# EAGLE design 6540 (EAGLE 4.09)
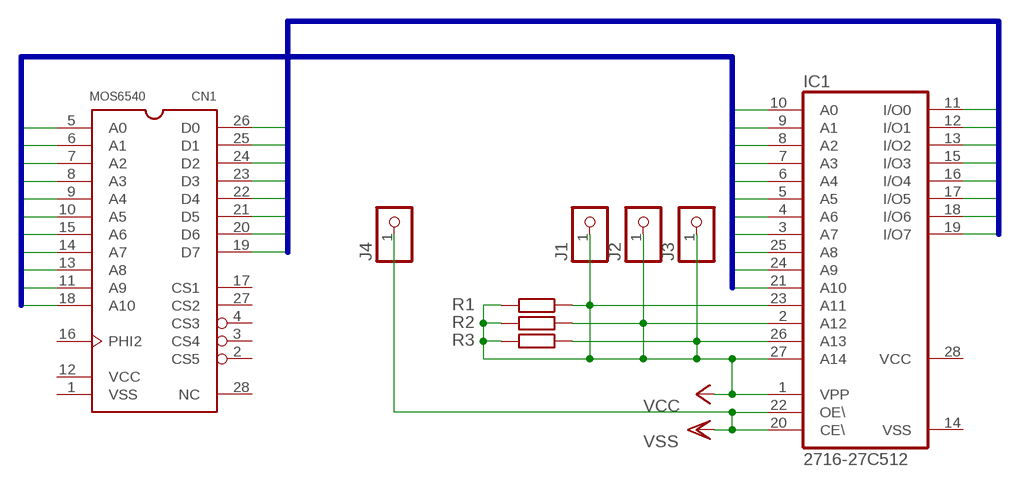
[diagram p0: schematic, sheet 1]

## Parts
CN1  MOS6540  [DIP-28]
IC1  2716-27C512  27C256AG  [DIL28-6]
J1  PINHD-1X1  [1X01]
J2  PINHD-1X1  [1X01]
J3  PINHD-1X1  [1X01]
J4  PINHD-1X1  [1X01]
R1  R-EU_M0805  [M0805]
R2  R-EU_M0805  [M0805]
R3  R-EU_M0805  [M0805]

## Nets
A0: CN1.5(A0) IC1.10(A0)
A1: CN1.6(A1) IC1.9(A1)
A2: CN1.7(A2) IC1.8(A2)
A3: CN1.8(A3) IC1.7(A3)
A4: CN1.9(A4) IC1.6(A4)
A5: CN1.10(A5) IC1.5(A5)
A6: CN1.15(A6) IC1.4(A6)
A7: CN1.14(A7) IC1.3(A7)
A8: CN1.13(A8) IC1.25(A8)
A9: CN1.11(A9) IC1.24(A9)
A10: CN1.18(A10) IC1.21(A10)
D0: CN1.26(D0) IC1.11(I/O0)
D1: CN1.25(D1) IC1.12(I/O1)
D2: CN1.24(D2) IC1.13(I/O2)
D3: CN1.23(D3) IC1.15(I/O3)
D4: CN1.22(D4) IC1.16(I/O4)
D5: CN1.21(D5) IC1.17(I/O5)
D6: CN1.20(D6) IC1.18(I/O6)
D7: CN1.19(D7) IC1.19(I/O7)
VCC: IC1.1(VPP) IC1.2(A12) IC1.23(A11) IC1.26(A13) IC1.27(A14) J1.1 J2.1 J3.1 R1.1 R1.2 R2.1 R2.2 R3.1 R3.2
VSS: IC1.20(CE\) IC1.22(OE\) J4.1
Unconnected: CN1.2(CS5) CN1.3(CS4) CN1.4(CS3) CN1.16(PHI2) CN1.17(CS1) CN1.27(CS2) CN1.28(NC)

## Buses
A[0..10]
D[0..7]

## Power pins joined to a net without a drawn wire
VCC: CN1.12(VCC) IC1.28(VCC)
VSS: CN1.1(VSS) IC1.14(VSS)

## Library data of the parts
CN1 = 65XXX:MOS6540
IC1 = memory-hitachi:27C256AG: MEMORY
J1-J4 = pinhead:PINHD-1X1: PIN HEADER
R1-R3 = rcl:R-EU_: RESISTOR, European symbol

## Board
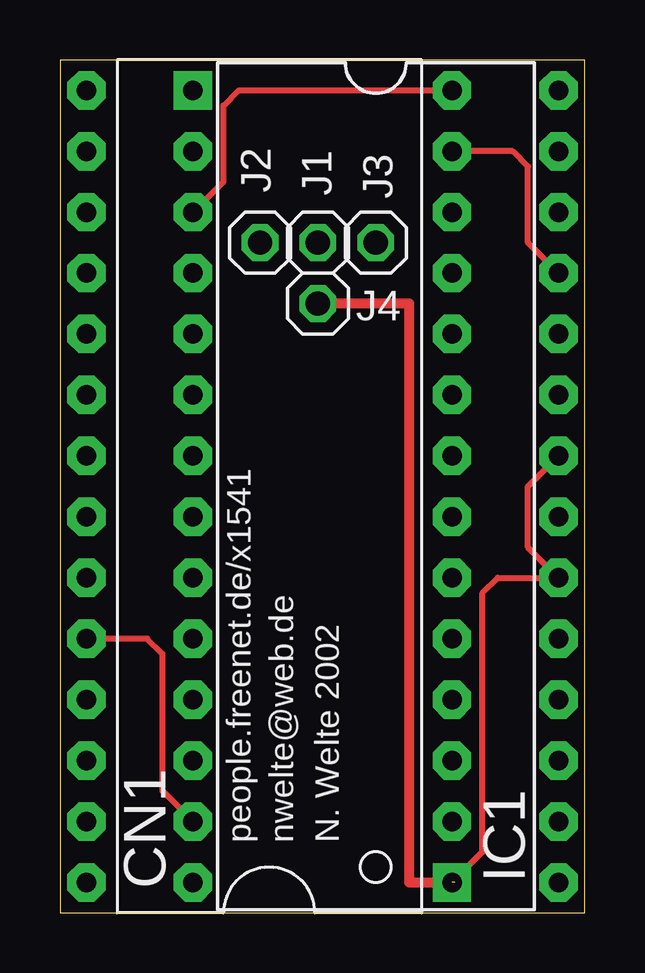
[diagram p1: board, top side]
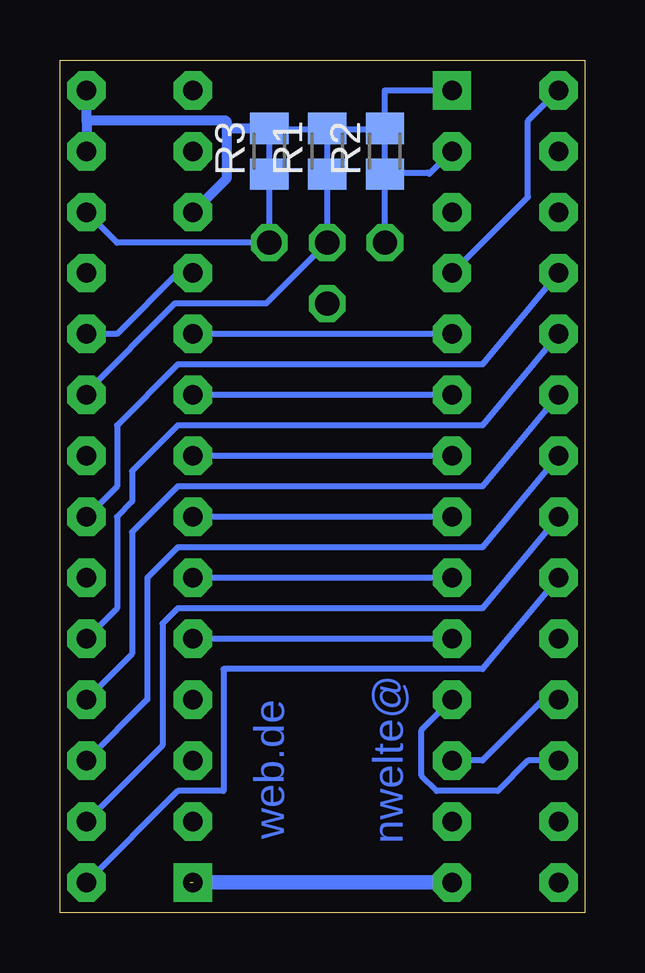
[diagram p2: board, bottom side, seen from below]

Size 21.89 x 35.55 mm. Coordinates in mm from the lower left corner, seen from the top.
Outline: 0,0 21.89,0 21.89,35.55 0,35.55 0,0
Copper layers used: Top, Bottom

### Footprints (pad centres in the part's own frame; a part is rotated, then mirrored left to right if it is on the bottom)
DIP-28 = drill 0.813 pad 1.6 square: 1 -15.24,-7.62 | drill 0.813 pad 1.6 octagon: 2 -12.7,-7.62; 3 -10.16,-7.62; 4 -7.62,-7.62; 5 -5.08,-7.62; 6 -2.54,-7.62; 7 0,-7.62; 8 2.54,-7.62; 9 5.08,-7.62; 10 7.62,-7.62; 11 10.16,-7.62; 12 12.7,-7.62; 13 15.24,-7.62; 14 17.78,-7.62; 15 17.78,7.62; 16 15.24,7.62; 17 12.7,7.62; 18 10.16,7.62; 19 7.62,7.62; 20 5.08,7.62; 21 2.54,7.62; 22 0,7.62; 23 -2.54,7.62; 24 -5.08,7.62; 25 -7.62,7.62; 26 -10.16,7.62; 27 -12.7,7.62; 28 -15.24,7.62
DIL28-6 = drill 0.813 pad 1.6 square: 1 -16.51,-7.62 | drill 0.813 pad 1.6 octagon: 2 -13.97,-7.62; 3 -11.43,-7.62; 4 -8.89,-7.62; 5 -6.35,-7.62; 6 -3.81,-7.62; 7 -1.27,-7.62; 8 1.27,-7.62; 9 3.81,-7.62; 10 6.35,-7.62; 11 8.89,-7.62; 12 11.43,-7.62; 13 13.97,-7.62; 14 16.51,-7.62; 15 16.51,7.62; 16 13.97,7.62; 17 11.43,7.62; 18 8.89,7.62; 19 6.35,7.62; 20 3.81,7.62; 21 1.27,7.62; 22 -1.27,7.62; 23 -3.81,7.62; 24 -6.35,7.62; 25 -8.89,7.62; 26 -11.43,7.62; 27 -13.97,7.62; 28 -16.51,7.62
1X01 = drill 1.016 octagon: 1 0,0
M0805 = smd 1.3 x 1.6: 1 -0.95,0; 2 0.95,0

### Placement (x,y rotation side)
CN1  8.72,16.51 90 top
IC1  13.17,17.78 270 top
J1  10.76,27.94 0 top
J2  8.34,27.94 0 top
J3  13.17,27.94 0 top
J4  10.76,25.39 0 top
R1  10.76,31.75 90 bottom
R2  8.34,31.75 90 bottom
R3  13.17,31.75 90 bottom

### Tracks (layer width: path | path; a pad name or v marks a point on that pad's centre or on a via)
A0
  Bottom 0.254: IC1.10 CN1.5
A1
  Bottom 0.254: IC1.9 CN1.6
A2
  Bottom 0.254: IC1.8 CN1.7
A3
  Bottom 0.254: IC1.7 CN1.8 15.71,19.05
A4
  Bottom 0.254: IC1.6 CN1.9
A5
  Bottom 0.254: IC1.5 CN1.10
A6
  Bottom 0.254: IC1.4 2.38,29.84 2.38,33.02 CN1.15
A7
  Top 0.254: IC1.3 6.82,30.48 6.82,33.65 7.46,34.28 CN1.14
A8
  Top 0.254: CN1.13 18.88,31.75 19.52,31.11 19.52,27.94 IC1.25
A9
  Bottom 0.254: IC1.24 19.52,24.12 16.98,26.67 CN1.11
A10
  Bottom 0.254: CN1.18 4.28,22.86 16.98,22.86 19.52,20.32 19.52,17.78 IC1.21
D0
  Bottom 0.254: CN1.26 2.38,6.34 3.65,5.08 6.18,5.08 6.82,5.71 6.82,7.62 IC1.11
D1
  Bottom 0.254: CN1.25 1.74,8.88 4.28,6.34 IC1.12
D2
  Top 0.254: IC1.13 4.28,5.08 4.28,10.79 3.65,11.42 CN1.24
D3
  Bottom 0.254: CN1.23 4.28,10.15 15.07,10.15 15.07,5.08 16.98,5.08 IC1.15
D4
  Bottom 0.254: CN1.22 4.28,12.69 16.98,12.69 17.61,12.06 17.61,6.98 IC1.16
D5
  Bottom 0.254: CN1.21 4.28,15.23 16.98,15.23 18.25,13.96 18.25,8.88 IC1.17
D6
  Bottom 0.254: CN1.20 4.28,17.78 16.98,17.78 18.88,15.87 18.88,10.79 IC1.18
D7
  Bottom 0.254: CN1.19 4.28,20.32 16.98,20.32 18.88,18.41 18.88,17.14 19.52,16.51 19.52,12.69 IC1.19
VCC
  Bottom 0.254: IC1.1 8.34,34.28 8.34,32.76 8.6,33.02 8.66,33.02 | 13.42,32.7 13.42,32.63 13.23,32.63 13.17,32.57 | 10.76,32.63 R1.2 10.7,32.63 8.4,32.63 R2.2 | 10.76,32.63 13.11,32.63 R3.2 13.17,32.57 | 13.17,32.57 13.17,32.51 R3.1 J3.1 19.52,27.94 IC1.26 | R2.2 8.66,33.02 | 8.66,33.02 8.72,33.02 | IC1.23 20.79,21.71 17.11,25.39 13.3,25.39 J1.1 R1.1 10.76,32.63 | IC1.2 6.5,30.8 6.56,30.86 8.34,30.86 | 8.34,30.86 R2.1 8.34,30.6 | J2.1 8.34,30.6 | 8.34,30.6 8.22,30.73 | 8.34,30.86 R2.2
  Bottom 0.406: 20.79,33.02 IC1.28 | 13.42,32.7 14.89,32.7 14.95,33.02 | 14.95,33.02 14.95,30.6 CN1.12 | 14.95,33.02 20.79,33.02 | 20.79,33.02 IC1.27 | 13.17,32.51 13.17,32.38
VSS  (1 unrouted)
  Top 0.254: CN1.1 17.61,2.54 17.61,13.33 18.25,13.96 IC1.20 19.52,15.23 19.52,17.78 IC1.22
  Top 0.406: J4.1 14.57,25.39 14.57,1.27 16.47,1.27
  Bottom 0.61: IC1.14 10.63,1.27 CN1.1

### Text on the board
Bottom: nwelte@ | web.de
tNames: people.freenet.de/x1541 | nwelte@web.de | N. Welte 2002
